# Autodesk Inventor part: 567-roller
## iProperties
Author: Administrator
Shininess: 64.0
Angle Display Precision: 2
Document Length Units: 11272
Document Angle Units: 11286
Document Time Units: 11279
Document Mass Units: 11290
Document Length Units Precision: 3
Document Angle Units Precision: 2
Compacted: True
PropertySet Name: _Private Model Information
Created: 2002-03
Part Number: 567-roller
Material: Stainless Steel, 440C
Document SubType Name: Modeling
Designer: Administrator
Control State: 0
Master: False
Checked Out: False
PropertySet Name: Design Tracking Control
Density: 0.0
Volumn: 0.0
Area: 0.0
PropertySet Name: Model Information
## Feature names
1. Revolution1
